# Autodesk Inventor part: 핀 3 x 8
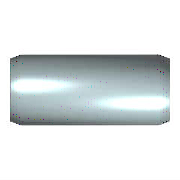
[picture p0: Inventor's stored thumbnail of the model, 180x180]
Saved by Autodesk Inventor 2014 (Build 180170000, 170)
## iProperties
IsCustomPart: 1
Created: 2012-02
Part Number: 핀 3 x 8
Material: 강철, 연강
Description: 평행 핀
Document SubType Name: Modeling
Standard: KS B 1320
Designer: mduedu
Standards Organization: KS
Language: ko-KR
Size Designation: B 3 x  8
Categories: <MemberInstance><Categories><Category DisplayName="조임쇠" InternalName="e4da775c-781d-43d5-af7c-5136215cf5a6" Mnemonic="FSTN"><Category DisplayName="핀" InternalNa
Density: 1 g/cm^3
Appearance: 노란색
Author: mduedu
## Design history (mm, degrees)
sketch "스케치"
  geometry: C1 r 1.5 at (0, 0); 1 further point
  constraints: 1 centre point, 1 coincident
  dimensions: "d1" = 3 diameter of C1 (= NND)
extrude "본체" new body sketch "스케치" distance "d2" = 8 (= NLG); taper "d3" = 0 deg
chamfer "스케치2" distance "d8" = 0.5 (= PHH); stored, may be unused: angle "d9" = 15 deg (= FAWI), second distance "d12" = 0.5 (= PHH)
body "Solid1"
chamfer "모따기1" distance "d4" = 0.5 (= PHH); stored, may be unused: angle "d5" = 15 deg (= FAWI), second distance "d11" = 0.5 (= PHH)
other parameters: "NND" = 3 [user parameter; used in 1 equation term], "NLG" = 8 [user parameter; used in 1 equation term], "PHH" = 0.5 [user parameter; used in 4 equation terms], "FAWI" = 15 deg [user parameter; used in 2 equation terms], "d13" = 0, "d15" = 0, "d16" = 0, "KAH" = 0.4 [user parameter]
